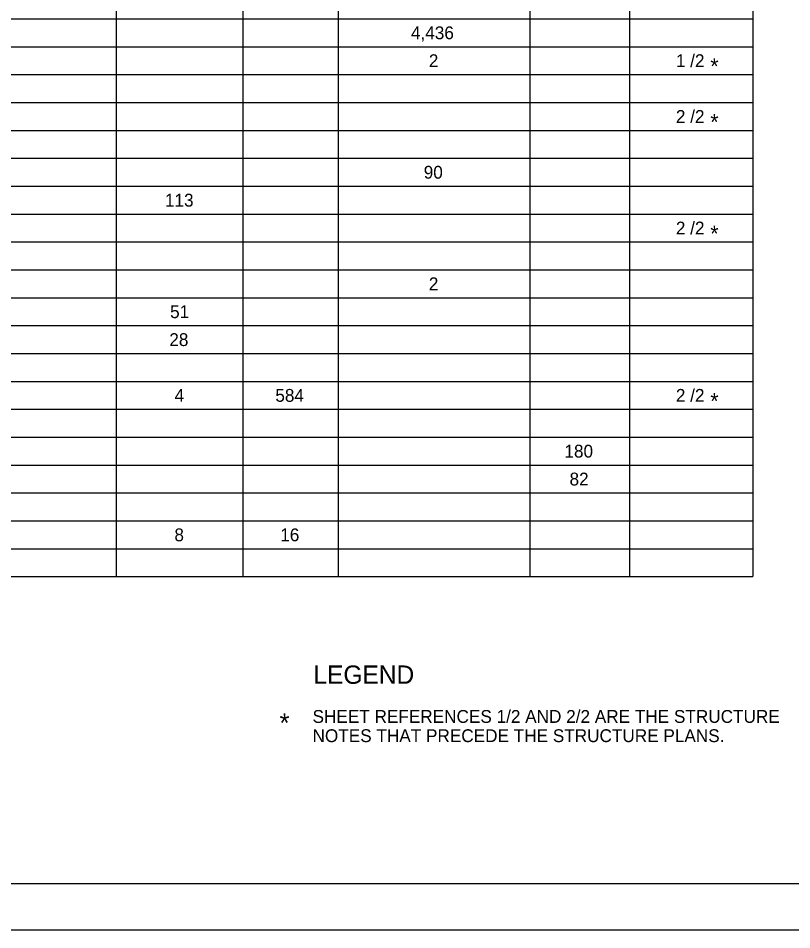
# Model space of a CAD drawing. Extents: x 0 to 34, y 0 to 22.
# Drawn here: x 20.09 to 28.52, y 0 to 9.94 of the extents above; entities that cross this region are included whole.
import ezdxf

# ---------------------------------------------------------------- set-up
doc = ezdxf.new("R2010")
doc.units = 0
for name, color, linetype in [('SH_Border', 7, 'Continuous'), ('SH_Cut_Line', 7, 'Continuous'), ('SH_Text', 7, 'Continuous')]:
    doc.layers.add(name, color=color, linetype=linetype)

msp = doc.modelspace()

# ---------------------------------------------------------------- linework, layer by layer
at = {"layer": 'SH_Border'}
msp.add_lwpolyline([(1.5, 21.5), (33.5, 21.5), (33.5, 0.5), (1.5, 0.5)], close=True, dxfattribs=at)
at = {"layer": 'SH_Cut_Line'}
msp.add_lwpolyline([(0, 0), (34, 0), (34, 22), (0, 22)], close=True, dxfattribs=at)
at = {"layer": 'SH_Text'}
for p, q in [((28.0995, 18.4529), (28.0995, 3.8513)), ((21.1536, 17.8445), (21.1536, 3.8513)), ((22.5352, 17.8445), (22.5352, 3.8513)), ((23.5745, 17.8445), (23.5745, 3.8513)), ((25.6659, 17.8445), (25.6659, 3.8513)), ((26.756, 17.8445), (26.756, 3.8513)), ((5.5887, 9.9353), (28.0995, 9.9353)), ((5.5887, 9.6311), (28.0995, 9.6311)), ((5.5887, 9.3269), (28.0995, 9.3269)), ((5.5887, 9.0227), (28.0995, 9.0227)), ((5.5887, 8.7185), (28.0995, 8.7185)), ((5.5887, 8.4143), (28.0995, 8.4143)), ((5.5887, 8.1101), (28.0995, 8.1101)), ((5.5887, 7.8059), (28.0995, 7.8059)), ((5.5887, 7.5017), (28.0995, 7.5017)), ((5.5887, 7.1975), (28.0995, 7.1975)), ((5.5887, 6.8933), (28.0995, 6.8933)), ((5.5887, 6.5891), (28.0995, 6.5891)), ((5.5887, 6.2849), (28.0995, 6.2849)), ((5.5887, 5.9807), (28.0995, 5.9807)), ((5.5887, 5.6765), (28.0995, 5.6765)), ((5.5887, 5.3723), (28.0995, 5.3723)), ((5.5887, 5.0681), (28.0995, 5.0681)), ((5.5887, 4.7639), (28.0995, 4.7639)), ((5.5887, 4.4597), (28.0995, 4.4597)), ((5.5887, 4.1555), (28.0995, 4.1555)), ((5.5887, 3.8513), (28.0995, 3.8513))]:
    msp.add_line(p, q, dxfattribs=at)

# ---------------------------------------------------------------- texts
for s, height, p in [('4,436', 0.13993, (24.3699, 9.7132)), ('2', 0.1399, (24.5653, 9.409)), ('1 /2', 0.13993, (27.2606, 9.409)), ('*', 0.175, (27.6356, 9.3312)), ('2 /2', 0.13993, (27.2606, 8.8006)), ('*', 0.175, (27.6356, 8.7228)), ('90', 0.13993, (24.5095, 8.1922)), ('113', 0.13993, (21.6862, 7.888)), ('2 /2', 0.13993, (27.2606, 7.5838)), ('*', 0.175, (27.6356, 7.5052)), ('2', 0.1399, (24.5653, 6.9754)), ('51', 0.13993, (21.7421, 6.6712)), ('28', 0.13993, (21.7337, 6.367)), ('4', 0.1399, (21.7912, 5.7586)), ('584', 0.13993, (22.8906, 5.7586)), ('2 /2', 0.13993, (27.2606, 5.7586)), ('*', 0.175, (27.6356, 5.6791)), ('180', 0.13993, (26.0446, 5.1502)), ('82', 0.13993, (26.1005, 4.846)), ('8', 0.1399, (21.7893, 4.2376)), ('16', 0.13993, (22.9439, 4.2376)), ('LEGEND', 0.2, (23.3059, 2.6827)), ('SHEET REFERENCES 1/2 AND 2/2 ARE THE STRUCTURE', 0.14, (23.2965, 2.2567)), ('*', 0.21, (22.9365, 2.1518)), ('NOTES THAT PRECEDE THE STRUCTURE PLANS.', 0.14, (23.2965, 2.0467))]:
    msp.add_text(s, height=height, dxfattribs=at).set_placement(p)

doc.saveas('drawing.dxf')
